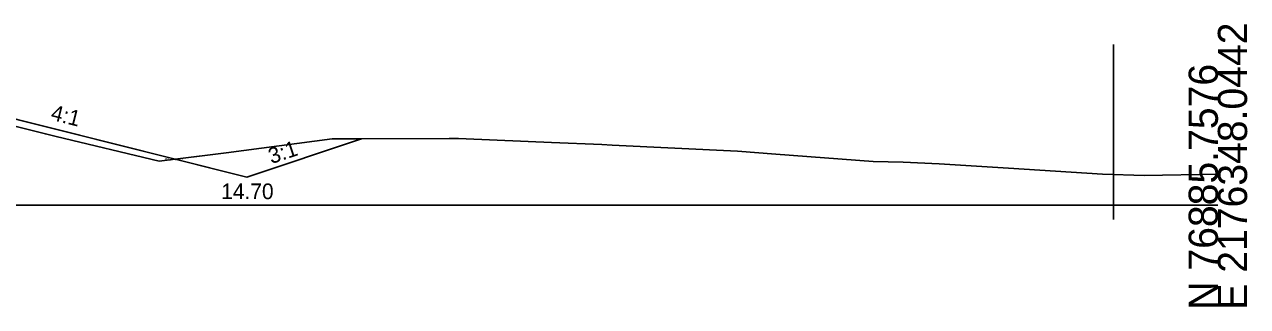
# Model space of a CAD drawing. Extents: x 2177029 to 2201446, y 59897 to 78390.
# Drawn here: x 2199328.4 to 2199445.6, y 68397.6 to 68424.6 of the extents above; entities that cross this region are included whole.
import ezdxf

# ---------------------------------------------------------------- set-up
doc = ezdxf.new("R2010")
doc.units = 0
for name, color, linetype in [('Exist Cross Section Cell', 7, 'Continuous'), ('Exist PHM Roadway Shape', 7, 'Continuous'), ('Exist XS Ground Line', 7, 'Continuous'), ('Prop CMT Guardrail Widen Shoulder', 7, 'Continuous'), ('Prop CMT Top Wall Envelope', 7, 'Continuous'), ('Prop Hatching', 7, 'Continuous'), ('Prop XS Side Slope Text', 7, 'Continuous'), ('Scratch_Level_2', 7, 'Continuous')]:
    doc.layers.add(name, color=color, linetype=linetype)

msp = doc.modelspace()

# ---------------------------------------------------------------- linework, layer by layer
at = {"layer": 'Exist Cross Section Cell'}
msp.add_line((2199242.73, 68407.31), (2199442.73, 68407.31), dxfattribs=at)
at = {"layer": 'Exist XS Ground Line'}
msp.add_lwpolyline([(2199322.65, 68416.05), (2199330.38, 68414.13), (2199331.42, 68413.88), (2199341.27, 68411.54), (2199347.72, 68412.33), (2199357.87, 68413.67), (2199369.06, 68413.69), (2199369.96, 68413.68), (2199370.71, 68413.67), (2199378.87, 68413.32), (2199383.71, 68413.13), (2199384.7, 68413.07), (2199396.7, 68412.47), (2199400.36, 68412.19), (2199409.69, 68411.5), (2199412.57, 68411.43), (2199416.03, 68411.28), (2199422.68, 68410.85), (2199431.69, 68410.27), (2199435.67, 68410.15), (2199442.73, 68410.27)], dxfattribs=at)
at = {"layer": 'Prop Hatching'}
msp.add_line((2199349.68, 68410.01), (2199360.66, 68413.67), dxfattribs=at)
msp.add_lwpolyline([(2199318.74, 68417.24), (2199320.74, 68417.24), (2199349.68, 68410.01)], dxfattribs=at)
at = {"layer": 'Prop XS Side Slope Text'}
for points in [[(2199324.74, 68416.24), (2199342.81, 68411.73), (2199341.27, 68411.54), (2199331.42, 68413.88), (2199330.38, 68414.13), (2199322.65, 68416.05), (2199318.28, 68416.24), (2199319.74, 68416.24)], [(2199342.81, 68411.73), (2199347.72, 68412.33), (2199357.87, 68413.67), (2199360.66, 68413.67), (2199349.68, 68410.01)]]:
    msp.add_lwpolyline(points, close=True, dxfattribs=at)
at = {"layer": 'Scratch_Level_2'}
msp.add_line((2199432.73, 68405.94), (2199432.73, 68422.68), dxfattribs=at)

# ---------------------------------------------------------------- texts
at = {"layer": 'Exist Cross Section Cell'}
for s, p in [('E 2176348.0442', (2199445.53, 68397.31)), ('N 76885.7576', (2199442.73, 68397.31))]:
    msp.add_text(s, height=2.8, rotation=90, dxfattribs=at).set_placement(p)
at = {"layer": 'Exist PHM Roadway Shape'}
msp.add_text('RT_Slope_Fill', height=0.2, dxfattribs=at).set_placement((2199341.86, 68411.63))
at = {"layer": 'Prop CMT Guardrail Widen Shoulder'}
msp.add_text('4:1', height=1.5, rotation=345.9647, dxfattribs=at).set_placement((2199330.81, 68415.5))
at = {"layer": 'Prop CMT Top Wall Envelope'}
msp.add_text('3:1', height=1.5, rotation=18.4349, dxfattribs=at).set_placement((2199352.04, 68411.24))
msp.add_text('14.70', height=1.5, dxfattribs=at).set_placement((2199347.23, 68407.89))

doc.saveas('drawing.dxf')
